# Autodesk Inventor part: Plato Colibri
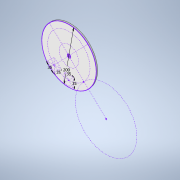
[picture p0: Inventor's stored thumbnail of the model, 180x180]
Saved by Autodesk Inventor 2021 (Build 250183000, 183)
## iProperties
Created: 2021-03
Part Number: Plato Colibri
Material: Genérico
Document SubType Name: Modeling
Designer: ATOUZA
Density: 1 g/cm^3
Appearance: Valor por defecto
Author: ATOUZA
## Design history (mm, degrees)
sketch "Boceto1"
  geometry: L1 (0, 0)-(136.919, -132.703); L2 (-17.5, -95.3)-(17.5, -95.3); L3 (17.5, -95.3)-(17.5, -60.3); L4 (17.5, -60.3)-(-17.5, -60.3); L5 (-17.5, -60.3)-(-17.5, -95.3); L6 (-17.5, -95.3)-(17.5, -60.3); L7 (17.5, -95.3)-(-17.5, -60.3); L8 (0, 0)-(-69.597, -71.807); L9 (0, 0)-(69.597, 71.807); L10 (0, 0)-(-71.807, 69.597); L11 (-78.892, -56.253)-(-53.759, -80.612); L12 (-53.759, -80.612)-(-29.4, -55.479); L13 (-29.4, -55.479)-(-54.533, -31.12); L14 (-54.533, -31.12)-(-78.892, -56.253); L15 (-78.892, -56.253)-(-29.4, -55.479); L16 (-53.759, -80.612)-(-54.533, -31.12); C1 r 6.4 at (0, 0) reference; C2 r 35.5 at (0, 0) reference; C3 r 3 at (136.919, -132.703) reference; C4 r 2.479 at (53.913, -56.213) reference; C5 r 6.4 at (0, 0); C6 r 100 at (0, 0); C7 r 2 at (54.146, 55.866); C8 r 2 at (-55.866, 54.146); C9 r 2 at (-54.146, -55.866); C10 r 2 at (55.866, -54.146); A1 r 112.875 centre (136.919, -132.703) between (53.913, -56.213) and (55.866, -54.146); A2 r 77.8 centre (0, 0) between (0, -77.8) and (-54.146, -55.866); A3 r 100 centre (0, 0) between (-69.597, -71.807) and (69.597, 71.807); 1 further point
  constraints: 32 end point, 10 point on circle, 9 centre point, 6 coincident, 4 midpoint, 4 parallel, 4 perpendicular, 4 point on line, 2 concentric, 1 horizontal
  dimensions: "d0" = 35 distance of L4.end L3.end; "d1" = 35 distance of L3.end L2.end; "d2" = 200 diameter of A3; "d3" = 35 distance of L11.start L11.end; "d4" = 35 distance of L12.end L11.end; "d16" = 4 diameter of C7; "d17" = 4 diameter of C8; "d18" = 4 diameter of C9; "d19" = 4 diameter of C10
extrude "Extrusión1" new body sketch "Boceto1" distance "d5" = 5.5; taper "d6" = 0 deg
sketch "Boceto2"
  geometry: L1 (0, 0)-(136.919, -132.703); L2 (-17.5, -95.3)-(17.5, -95.3); L3 (17.5, -95.3)-(17.5, -60.3); L4 (17.5, -60.3)-(-17.5, -60.3); L5 (-17.5, -60.3)-(-17.5, -95.3); L6 (-17.5, -95.3)-(17.5, -60.3); L7 (17.5, -95.3)-(-17.5, -60.3); L8 (0, 0)-(-69.597, -71.807); L9 (0, 0)-(69.597, 71.807); L10 (0, 0)-(-71.807, 69.597); L11 (-78.892, -56.253)-(-53.759, -80.612); L12 (-53.759, -80.612)-(-29.4, -55.479); L13 (-29.4, -55.479)-(-54.533, -31.12); L14 (-54.533, -31.12)-(-78.892, -56.253); L15 (-78.892, -56.253)-(-29.4, -55.479); L16 (-53.759, -80.612)-(-54.533, -31.12); C1 r 6.4 at (0, 0); C2 r 35.5 at (0, 0); C3 r 3 at (136.919, -132.703); C4 r 6.4 at (0, 0); C5 r 100 at (0, 0); C6 r 2 at (54.146, 55.866); C7 r 2 at (-55.866, 54.146); C8 r 2 at (-54.146, -55.866); C9 r 2 at (55.866, -54.146); A1 r 77.8 centre (0, 0) between (0, -77.8) and (-54.146, -55.866); A2 r 100 centre (0, 0) between (-69.597, -71.807) and (69.597, 71.807); 3 further points
  constraints: 32 end point, 11 centre point, 8 point on circle, 6 coincident, 4 midpoint, 4 parallel, 4 perpendicular, 4 point on line, 2 concentric, 1 horizontal, 3 other
  dimensions: "d7" = 35 distance of L4.end L3.end; "d8" = 35 distance of L3.end L2.end; "d9" = 200 diameter of A2; "d10" = 35 distance of L11.start L11.end; "d11" = 35 distance of L12.end L11.end; "d12" = 4 diameter of C6; "d13" = 4 diameter of C7; "d14" = 4 diameter of C8; "d15" = 4 diameter of C9
node "Sólido1"
node "Referencia1"
node "Referencia2"
node "Referencia3"
node "Referencia4"
